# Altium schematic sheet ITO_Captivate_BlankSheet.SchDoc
size 431 x 279 mm; Date: Not shown in title block; ApprovedBy: Not shown in title block; CheckedBy: Not shown in title block; Author: Not shown in title block; CompanyName: Not shown in title block; Engineer: Not shown in title block; Organization: Not shown in title block; Address1: Not shown in title block; Address2: Not shown in title block; Address3: Not shown in title block; Address4: Not shown in title block; DocumentNumber: 1; Revision: Use project parameter SCH_Rev; SheetNumber: 2; SheetTotal: 3; PageSetup: Record=PageOptions¦CenterHorizontal=True¦CenterVertical=True¦PrintScale=1.00¦XCorrection=1.00¦YCorrection=1.00¦PrintKind=0¦BorderSize=5000000¦LeftOffset=0¦BottomOffset=0¦Orientation=2¦PaperLength=1000¦PaperWidth=1000¦Scale=100¦PaperSource=15¦PrintQuality=600¦MediaType=1¦DitherType=10¦PaperKind=Letter¦PrintScaleMode=1
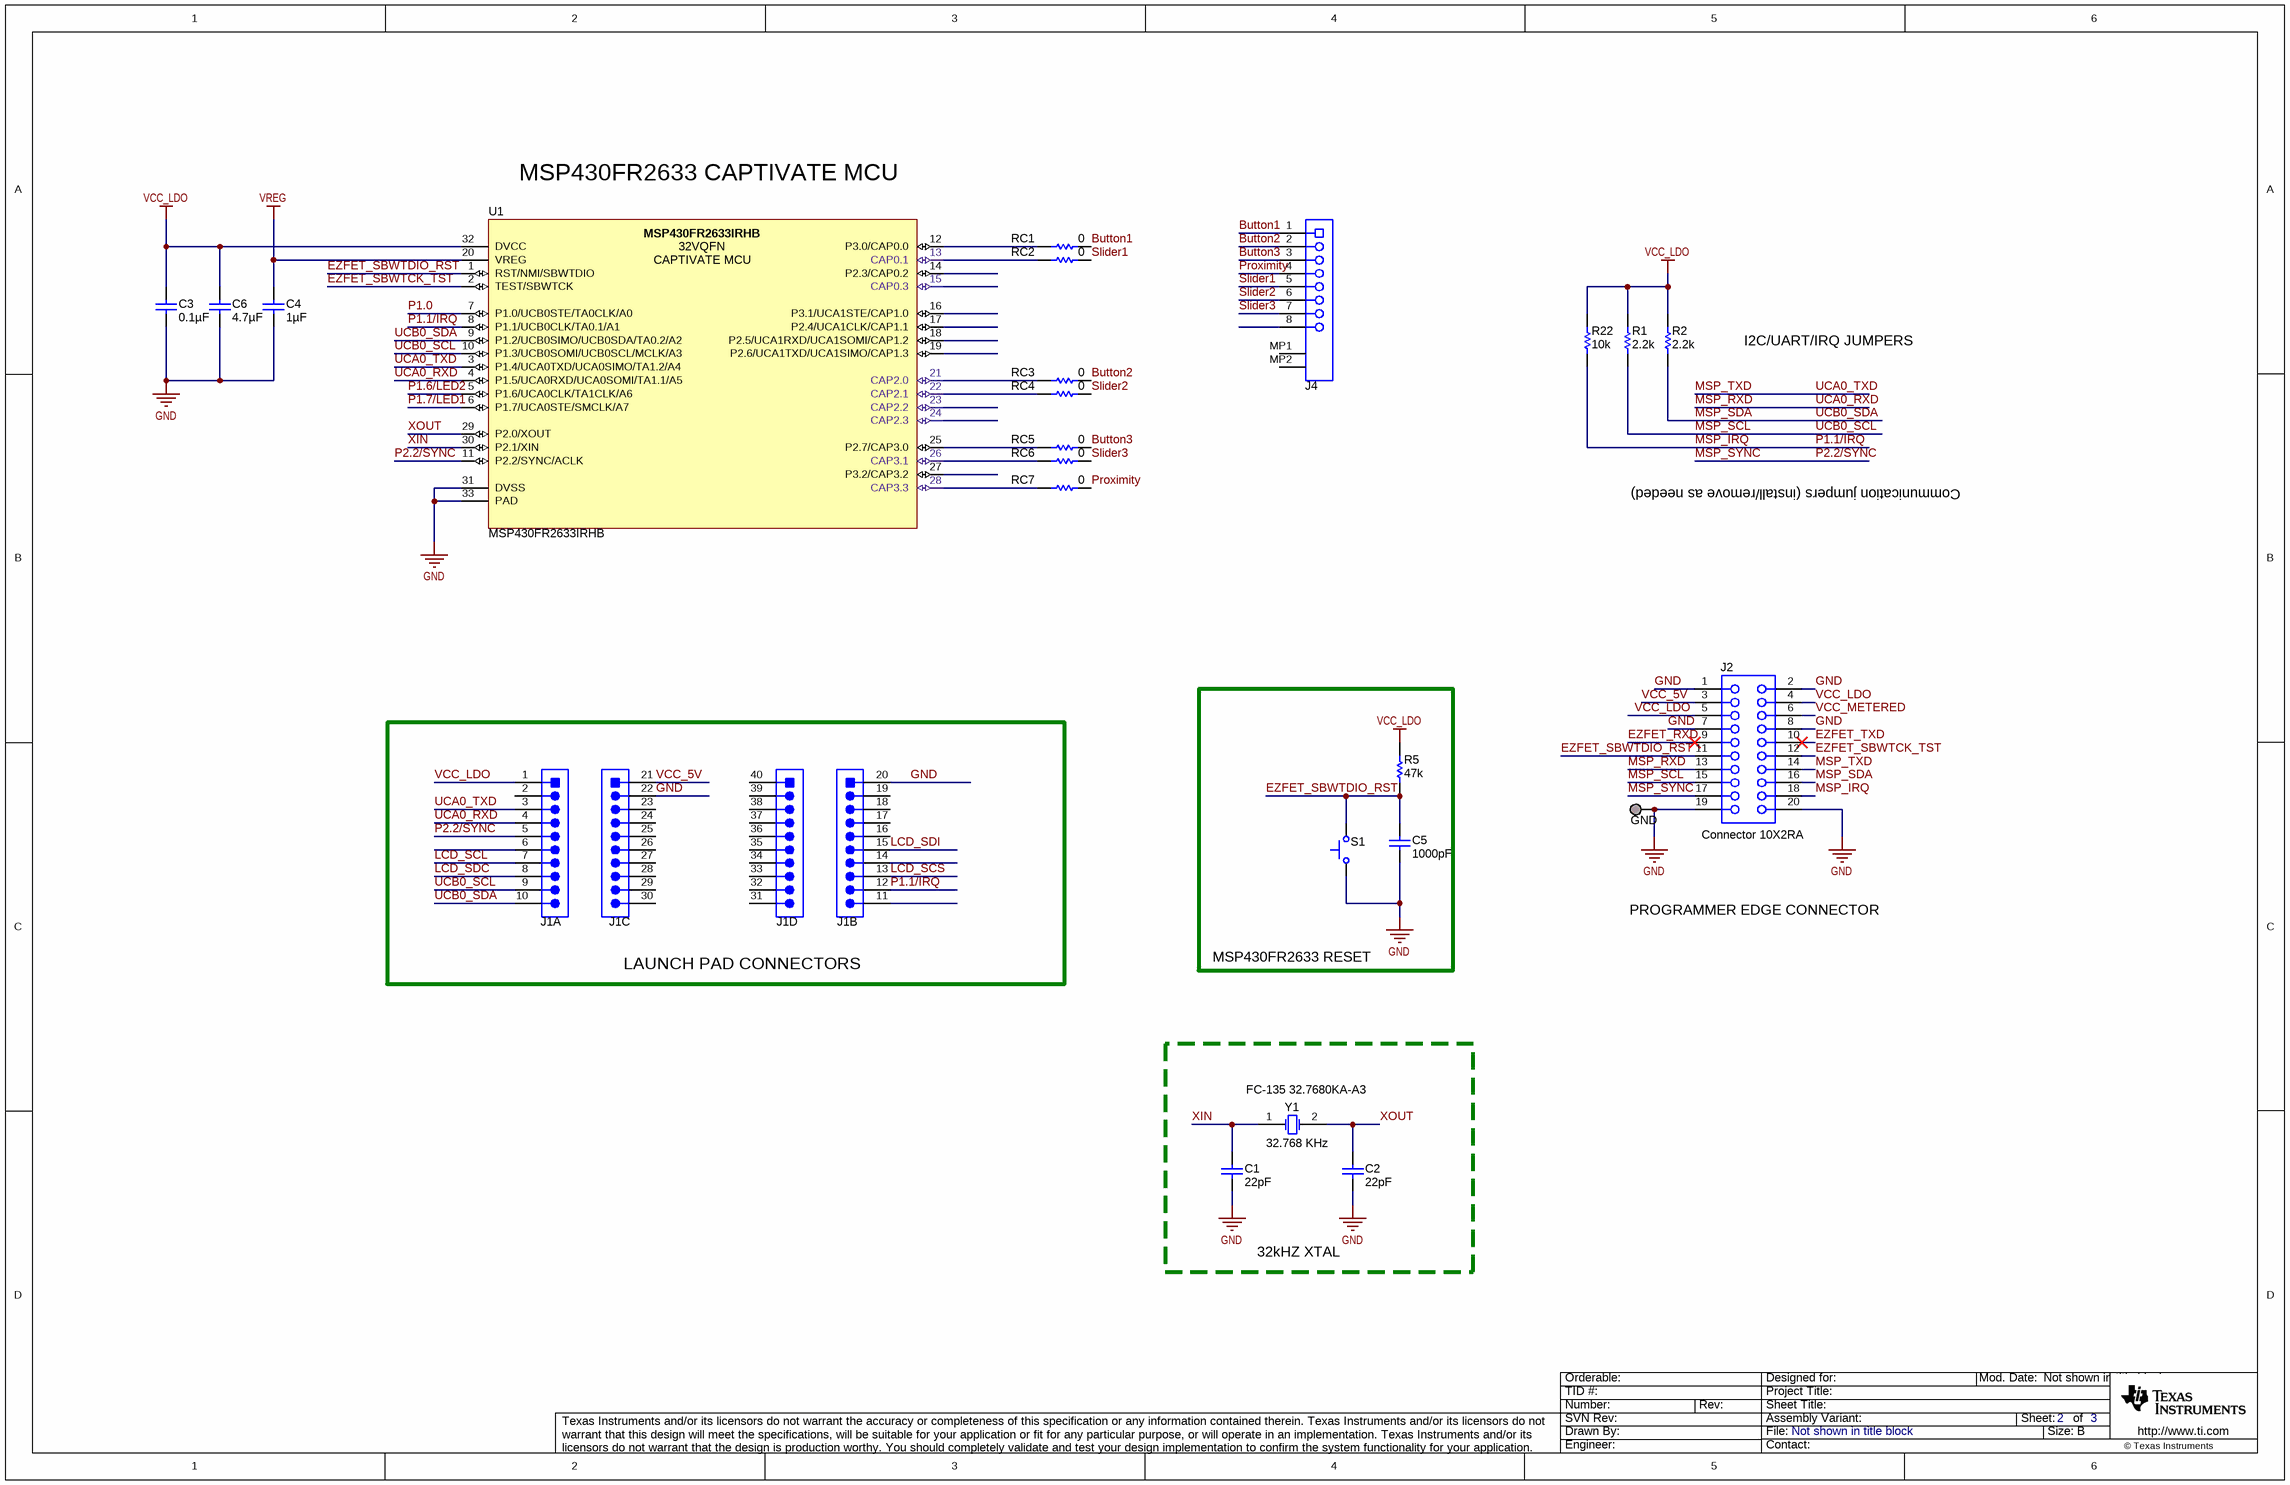
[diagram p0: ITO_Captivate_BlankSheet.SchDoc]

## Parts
C1  ValueDisplayed: 22pF  [0402]  (hidden comment: GRM1555C1H220JA01D)
C2  ValueDisplayed: 22pF  [0402]  (hidden comment: GRM1555C1H220JA01D)
C3  ValueDisplayed: 0.1µF  [0402]  (hidden comment: 885012205037)
C4  ValueDisplayed: 1µF  [0603]  (hidden comment: GRM188R61A105KA61D)
C5  ValueDisplayed: 1000pF  [0402]  (hidden comment: GRM155R61H102KA01D)
C6  ValueDisplayed: 4.7µF  [0603]  (hidden comment: GRM185C81A475ME11D)
GND  TESTPOINT  [TP_VIA_060RND040]  (value not drawn)  (no BOM)
J1  TSW-110-07-G-S  [40Pin BP]  (value not drawn)  (parts A,B,C,D of 4)
J2  Connector 10X2RA  [CONN2X10RA]
J4  686108148922  [Wurth_686108148922]  (value not drawn)
R1  ValueDisplayed: 2.2k  [0402]  (hidden comment: CRCW04022K20JNED)
R2  ValueDisplayed: 2.2k  [0402]  (hidden comment: CRCW04022K20JNED)
R5  value 47k  [0402]  (hidden comment: CRCW040247K0JNED)
R22  ValueDisplayed: 10k  [0402]  (hidden comment: CRCW040210K0JNED)
RC1  ValueDisplayed: 0  [0603]  (hidden comment: ERJ-3GEY0R00V)
RC2  ValueDisplayed: 0  [0603]  (hidden comment: ERJ-3GEY0R00V)
RC3  ValueDisplayed: 0  [0603]  (hidden comment: ERJ-3GEY0R00V)
RC4  ValueDisplayed: 0  [0603]  (hidden comment: ERJ-3GEY0R00V)
RC5  ValueDisplayed: 0  [0603]  (hidden comment: ERJ-3GEY0R00V)
RC6  ValueDisplayed: 0  [0603]  (hidden comment: ERJ-3GEY0R00V)
RC7  ValueDisplayed: 0  [0603]  (hidden comment: ERJ-3GEY0R00V)
S1  EVQ-21505R  [SW_EVQ-21x05]  (value not drawn)
U1  MSP430FR2633IRHB  [RHB0032E_NV]
Y1  FC-135 32.7680KA-A3  Frequency: 32.768 KHz  [Epson_FC-135]

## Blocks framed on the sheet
MSP430FR2633 RESET: C5 R5 S1
LAUNCH PAD CONNECTORS: J1
32kHZ XTAL: C1 C2 Y1

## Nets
GND: C1.2 C2.2 C3.2 C4.2 C5.2 C6.2 GND.1 J1.20 J1.22 J2.1 J2.2 J2.7 J2.8 J2.19 J2.20 S1.1 U1.31(DVSS) U1.33(PAD)
VCC_LDO: C3.1 C6.1 J1.1 J2.4 J2.5 R1.2 R2.2 R5.2 R22.2 U1.32(DVCC)
VREG: C4.1 U1.20(VREG)
Button1: J4.1 RC1.2
Button2: J4.2 RC3.2
Button3: J4.3 RC5.2
EZFET_RXD: J2.9
EZFET_SBWTCK_TST: J2.12 U1.2(TEST/SBWTCK)
EZFET_SBWTDIO_RST: C5.1 J2.11 R5.1 S1.2 U1.1(RST/NMI/SBWTDIO)
EZFET_TXD: J2.10
LCD_SCL: J1.7
LCD_SCS: J1.13
LCD_SDC: J1.8
LCD_SDI: J1.15
MSP_IRQ: J1.12 J2.18 R22.1 U1.8(P1.1/UCB0CLK/TA0.1/A1)  [also labelled P1.1/IRQ]
MSP_RXD: J1.4 J2.13 U1.4(P1.5/UCA0RXD/UCA0SOMI/TA1.1/A5)  [also labelled UCA0_RXD]
MSP_SCL: J1.9 J2.15 R1.1 U1.10(P1.3/UCB0SOMI/UCB0SCL/MCLK/A3)  [also labelled UCB0_SCL]
MSP_SDA: J1.10 J2.16 R2.1 U1.9(P1.2/UCB0SIMO/UCB0SDA/TA0.2/A2)  [also labelled UCB0_SDA]
MSP_SYNC: J1.5 J2.17 U1.11(P2.2/SYNC/ACLK)  [also labelled P2.2/SYNC]
MSP_TXD: J1.3 J2.14 U1.3(P1.4/UCA0TXD/UCA0SIMO/TA1.2/A4)  [also labelled UCA0_TXD]
P1.0: U1.7(P1.0/UCB0STE/TA0CLK/A0)
P1.6/LED2: U1.5(P1.6/UCA0CLK/TA1CLK/A6)
P1.7/LED1: U1.6(P1.7/UCA0STE/SMCLK/A7)
Proximity: J4.4 RC7.2
Slider1: J4.5 RC2.2
Slider2: J4.6 RC4.2
Slider3: J4.7 RC6.2
VCC_5V: J1.21 J2.3
VCC_METERED: J2.6
XIN: C1.1 U1.30(P2.1/XIN) Y1.1(OSC1)
XOUT: C2.1 U1.29(P2.0/XOUT) Y1.2(OSC2)
NetRC1_1: RC1.1 U1.12(P3.0/CAP0.0)
NetRC2_1: RC2.1 U1.13(CAP0.1)
NetRC3_1: RC3.1 U1.21(CAP2.0)
NetRC4_1: RC4.1 U1.22(CAP2.1)
NetRC5_1: RC5.1 U1.25(P2.7/CAP3.0)
NetRC6_1: RC6.1 U1.26(CAP3.1)
NetRC7_1: RC7.1 U1.28(CAP3.3)

Not connected (* = marked no-connect by the designer): J1 2 6 11 14 16 17 18 19 23 24 25 26 27 28 29 30 31 32 33 34 35 36 37 38 39 40; J4 8 MP1 MP2; U1 14(P2.3/CAP0.2) 15(CAP0.3) 16(P3.1/UCA1STE/CAP1.0) 17(P2.4/UCA1CLK/CAP1.1) 18(P2.5/UCA1RXD/UCA1SOMI/CAP1.2) 19(P2.6/UCA1TXD/UCA1SIMO/CAP1.3) 23(CAP2.2) 24(CAP2.3) 27(P3.2/CAP3.2)

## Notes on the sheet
- MSP430FR2633 CAPTIVATE MCU
- I2C/UART/IRQ JUMPERS
- Communication jumpers (install/remove as needed)
- PROGRAMMER EDGE CONNECTOR

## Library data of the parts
C1 C2 = GRM1555C1H220JA01D: CAP, CERM, 22 pF, 50 V, +/- 5%, C0G/NP0, 0402; Manufacturer: MuRata; Polarized: N; CompType: Capacitor; Value: 22pF; U/M: EA; Cap_F: 0.000000000022; Tolerance_%: 5; Value1: Unknown; VDC_V: 50; Value2: 50V; TaMin_C: -55; TaMax_C: 125
C3 = 885012205037: CAP, CERM, 0.1 µF, 16 V, +/- 10%, X7R, 0402; Manufacturer: Wurth Elektronik; Polarized: N; CompType: Capacitor; Value: 0.1uF; U/M: EA; Cap_F: 0.0000001; Tolerance_%: 10; Value1: Unknown; VDC_V: 16; Value2: 16V; TaMin_C: -55; TaMax_C: 125; SizeArea_mm2: 0.5; SizeAreaWB_mm2: 3; SizeX_mm: 1; SizeZ_mm: 0.6; AEC Category: Q200
C4 = GRM188R61A105KA61D: CAP, CERM, 1 µF, 10 V, +/- 10%, X5R, 0603; Manufacturer: MuRata; Polarized: N; CompType: Capacitor; Value: 1uF; U/M: EA; Cap_F: 0.000001; Tolerance_%: 10; Value1: Unknown; Value2: 10V; TaMin_C: -55; TaMax_C: 85; SizeArea_mm2: 1.28; SizeAreaWB_mm2: 4.68; SizeX_mm: 1.6; SizeY_mm: 0.8; SizeZ_mm: 1; AEC Category: Q200
C5 = GRM155R61H102KA01D: CAP, CERM, 1000 pF, 50 V, +/- 10%, X5R, 0402; Manufacturer: MuRata; Polarized: N; CompType: Capacitor; Value: 1000pF; U/M: EA; Cap_F: 0.000000001; Tolerance_%: 10; Value1: Unknown; VDC_V: 50; Value2: 50V; TaMin_C: -55; TaMax_C: 85; SizeArea_mm2: 0.5; SizeAreaWB_mm2: 3; SizeX_mm: 1; SizeZ_mm: 0.6; AEC Category: Q200
C6 = GRM185C81A475ME11D: CAP, CERM, 4.7 µF, 10 V, +/- 20%, X6S, 0603; Manufacturer: MuRata; Polarized: N; CompType: Capacitor; Value: 4.7uF; U/M: EA; Cap_F: 0.0000047; Tolerance_%: 20; Value1: Unknown; VDC_V: 10; Value2: 10V; TaMin_C: -55; TaMax_C: 105; SizeArea_mm2: 1.28; SizeAreaWB_mm2: 4.68; SizeX_mm: 1.6; SizeY_mm: 0.8; SizeZ_mm: 1; AEC Category: Q200
GND = TESTPOINT: TEST POINT.  No entry in BOM.
J1 = BoosterPack Connector: Header, 100mil, 10x1, Gold, TH; Manufacturer: Samtec; SymbolCreator: a0412235; U/M: EA
J2 = Connector 10X2RA: Connector, Female, 10-Pin, 2 row, Right Angle; Manufacturer: Samtec; PartNumber: SSW-110-22-F-D-RA; Alternate PartNumber: SSW-110-02-F-D-RA
J4 = 686108148922: FFC/FPC Connector, 8 POS, 1mm, Tin, R/A, SMT; Manufacturer: Wurth Elektronik; SymbolCreator: Altium; Pitch_mm: 1; Gender: Female; Voltage_V: 100; Cert_UL: Y
R1 R2 = CRCW04022K20JNED: RES, 2.2 k, 5%, 0.063 W, 0402; Manufacturer: Vishay-Dale; CompType: Resistor; Value: 2.2k; Res_ohm: 2200; Value_Code: 2k20; Tolerance_%: 5; Power_W: 0.063; Value2: 0.063W; VDC_V: 50; TempCo: 200 ppm/C; EIA_Code: E24; U/M: EA
R5 = CRCW040247K0JNED: RES, 47k ohm, 5%, 0.063W, 0402; Manufacturer: Vishay-Dale; CompType: Resistor; Res_ohm: 47000; Value_Code: 47k0; Tolerance_%: 5; Power_W: 0.063; VDC_V: 50; TempCo: 200 ppm/C; EIA_Code: E24; U/M: EA
R22 = CRCW040210K0JNED: RES, 10 k, 5%, 0.063 W, 0402; Manufacturer: Vishay-Dale; CompType: Resistor; Value: 10k; Res_ohm: 10000; Value_Code: 10k0; Tolerance_%: 5; Power_W: 0.063; Value2: 0.063W; VDC_V: 50; TempCo: 200 ppm/C; EIA_Code: E24; U/M: EA
RC1-RC7 = ERJ-3GEY0R00V: RES, 0, 5%, 0.1 W, 0603; Manufacturer: Panasonic; CompType: Resistor; Value: 0; Value_Code: 0000; Tolerance_%: 5; Power_W: 0.1; Value2: 0.1W; VDC_V: 50; TempCo: 600 ppm/C; SizeArea_mm2: 1.28; SizeX_mm: 1.6; SizeY_mm: 0.8; SizeZ_mm: 1; EIA_Code: E24; U/M: EA; AEC Category: Q200
S1 = EVQ-21505R: Switch, Tactile, SPST-NO, 0.02A, 15V, TH; Manufacturer: Panasonic; VDC_V: 15; SwitchFunction: Off-Mom; PositionCount: 1; CurrentRating_mA: 20
U1 = MSP430FR2633IRHB: MSP430 Captivate Microcontroller; Manufacturer: Texas Instruments; SymbolCreator: W. Schnoor; CompType: IC; U/M: EA, IN, or GM
Y1 = FC-135 32.7680KA-A3: Crystal, 32.768 KHz, 12.5 pF, SMD; Manufacturer: Epson; SymbolCreator: a0412235; U/M: EA; TaMin_C: -40; TaMax_C: 85; Frequency Stability: ±20ppm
